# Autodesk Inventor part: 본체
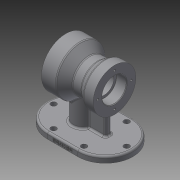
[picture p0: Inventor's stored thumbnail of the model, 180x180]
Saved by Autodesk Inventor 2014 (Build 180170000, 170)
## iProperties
Created: 2020-01
Part Number: 본체
Material: Generic
Document SubType Name: Modeling
Designer: kh
Density: 1 g/cm^3
Appearance: Default
Author: kh
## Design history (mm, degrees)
sketch "Sketch1"
  geometry: L1 (-25, 0)-(25, 0); L2 (-25, -45)-(25, -45); L3 (25, 45)-(-25, 45); L4 (25, 35)-(-25, 35); L5 (-25, -35)-(25, -35); C1 r 4.5 at (-25, 35); C2 r 4.5 at (-60, 0); C3 r 4.5 at (-25, -35); C4 r 4.5 at (60, 0); C5 r 4.5 at (25, 35); C6 r 4.5 at (25, -35); A1 r 45 centre (-25, 0) between (-25, 45) and (-25, -45); A2 r 45 centre (25, 0) between (25, -45) and (25, 45); A3 r 35 centre (-25, 0) between (-25, 35) and (-25, -35); A4 r 35 centre (25, 0) between (25, -35) and (25, 35); 1 further point
  constraints: 12 end point, 10 centre point, 10 point on circle, 4 coincident, 4 tangent, 2 parallel, 1 horizontal, 1 midpoint, 3 other
  dimensions: "d0" = 50 distance of L1.end L1.start; "d1" = 45 radius of A1; "d2" = 10 distance between parallel lines of L2 L5; "d3" = 9 diameter of C1; "d4" = 9 diameter of C2 (= d3); "d5" = 9 diameter of C3 (= d4); "d7" = 9 diameter of C4 (= d6); "d8" = 9 diameter of C5 (= d7); "d9" = 9 diameter of C6
extrude "Extrusion1" new body sketch "Sketch1" distance "d10" = 10; taper "d11" = 0 deg
sketch "Sketch2"
  geometry: L1 (40, 80)-(40, 120); L2 (40, 120)-(16, 120); L3 (16, 120)-(1.103, 107.5); L4 (1.103, 107.5)-(-13.289, 107.5); L5 (-13.289, 107.5)-(-24, 115); L6 (-24, 115)-(-40, 115); L7 (-40, 115)-(-40, 80); L8 (-40, 80)-(40, 80); L9 (70, 0)-(70, 10) reference; L10 (40, 106)-(20, 106); L11 (20, 106)-(20, 96); L12 (20, 96)-(-23, 96); L13 (-23, 96)-(-23, 100); L14 (-23, 100)-(-40, 100); 1 further point
  constraints: 26 end point, 5 parallel, 5 perpendicular, 2 point on line, 1 vertical
  dimensions: "d12" = 80 vertical distance of L7.end point (0, 0); "d13" = 30 distance between parallel lines of L1 L9; "d14" = 80 horizontal distance of L6.end L1.end; "d15" = 80 diameter of L2 L8; "d16" = 24 distance of L1.end L2.end; "d18" = 40 deg angle of L4 L3; "d19" = 35 deg angle of L4 L5; "d20" = 16 distance of L5.end L6.end; "d21" = 70 diameter of L6 L8; "d22" = 55 diameter of L4 L8; "d23" = 20 distance of L10.start L10.end; "d24" = 17 distance of L13.end L14.end; "d25" = 52 diameter of L10 L8; "d26" = 40 diameter of L14 L8; "d27" = 32 diameter of L12 L8
revolve "Revolution1" sketch "Sketch2" stored, may be unused: angle "d28" = 90 deg
sketch "Sketch3"
  geometry: L1 (-5.981, -5)-(30, -5); L2 (30, -5)-(30, 5); L3 (30, 5)-(-5.981, 5); L4 (-5.981, 5)-(-5.981, -5); L5 (-5.981, -5)-(30, 5); L6 (30, -5)-(-5.981, 5); L7 (-60, 0)-(-70, 0); L8 (40, 35)-(40, -35) reference; C1 r 4.5 at (-60, 0) reference; C2 r 16 at (-12, 0); A1 r 45 centre (-25, 0) between (-25, 45) and (-25, -45) reference; 3 further points
  constraints: 14 end point, 3 midpoint, 2 horizontal alignment, 2 parallel, 2 perpendicular, 1 centre point, 1 horizontal, 1 point on circle
  dimensions: "d29" = 58 distance of C2.centre L7.end; "d30" = 16 radius of C2; "d31" = 10 distance between parallel lines of L1 L3; "d32" = 10 distance between parallel lines of L2 L8
extrude "Extrusion2" join sketch "Sketch3" stored distance "d33" = 10; taper "d34" = 0 deg
sketch "Sketch4"
  geometry: C1 r 20 at (0, 0) reference; 2 further points
  constraints: 1 horizontal alignment
  dimensions: "d35" = 27.5 distance of C1.centre point (-27.5, 0)
hole "Hole1" sketch "Sketch4" at (-27.5, 0) diameter "d36" = 3.459; stored, may be unused: countersink angle "d40" = 90 deg, drill point angle "d42" = 118 deg; dims "d37" = 9, "d38" = 4, "d39" = 2, "d41" = 11
pattern_circular "Circular Pattern1" dims angle "d44" = 360 deg
sketch "Sketch5"
  geometry: C1 r 40 at (0, 0) reference; 2 further points
  constraints: 1 horizontal alignment
  dimensions: "d46" = 33 distance of point (33, 0) C1.centre
hole "Hole2" sketch "Sketch5" at (33, 0) diameter "d47" = 3.459; stored, may be unused: countersink angle "d51" = 90 deg, drill point angle "d53" = 118 deg; dims "d48" = 9, "d49" = 4, "d50" = 2, "d52" = 11
pattern_circular "Circular Pattern2" dims angle "d55" = 360 deg
sketch "Sketch6"
  geometry: L1 (0, 0)-(50, 0) reference; L2 (-45, 0)-(-45, 10) reference; 3 further points
  constraints: 1 midpoint, 1 vertical alignment, 1 other
  dimensions: "d57" = 4 distance of point (25, 4) point (25, 0)
emboss "Emboss1" sketch "Sketch6" dims "d0" = 50, "d1" = 45, "d2" = 10, "d3" = 9, "d4" = 9 (= d3), "d5" = 9 (= d4), "d7" = 9 (= d6), "d8" = 9 (= d7), "d9" = 9, "d58" = 0.5, "d59" = 0
fillet "Fillet1" dims "d60" = 0.3, "d61" = 3
fillet "Fillet2" dims "d62" = 3
fillet "Fillet3" dims "d63" = 3
chamfer "Chamfer1" distance "d64" = 1; stored, may be unused: second distance "d65" = 2, angle "d66" = 45 deg
body "Solid1"
other parameters: "d6" = 9 (= d5)
